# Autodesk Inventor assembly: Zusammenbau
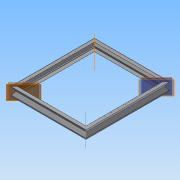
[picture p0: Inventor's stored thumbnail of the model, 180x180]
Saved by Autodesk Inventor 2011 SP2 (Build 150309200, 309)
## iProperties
Created: 2009-11
Part Number: Zusammenbau
Document SubType Name: Assembly
Designer: gkramp
Author: gkramp
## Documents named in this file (4)
- D:\InventorSchulung\Zusammenbau_Beispiel_Master\Zusammenbau.iam
- D:\InventorSchulung\Zusammenbau_Beispiel_Master\Masterbaugruppe.iam
- D:\InventorSchulung\Zusammenbau_Beispiel_Master\Rahmen_mit_Löchern.ipt
- D:\InventorSchulung\Zusammenbau_Beispiel_Master\Rahmen_ohne_Löcher.ipt
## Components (5 placed, 3 different names)
1. Masterbaugruppe:1 [sub-assembly] — Fluchtend:3
2. Rahmen_mit_Löchern:1 — Passend:1, Passend:2, Fluchtend:4, Passend:3
3. Rahmen_mit_Löchern:2 — Fluchtend:3, Fluchtend:4
4. Rahmen_ohne_Löcher:1 — Passend:3, Fluchtend:5, Fluchtend:6
5. Rahmen_ohne_Löcher:2 — Passend:4, Fluchtend:7, Passend:5
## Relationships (10: Flush 5, Mate 5)
- Fluchtend:3 [Flush]: Masterbaugruppe:1 ↔ Rahmen_mit_Löchern:2
- Passend:1 [Mate]: Rahmen_mit_Löchern:1
- Passend:2 [Mate]: Rahmen_mit_Löchern:1
- Fluchtend:4 [Flush]: Rahmen_mit_Löchern:1 ↔ Rahmen_mit_Löchern:2
- Passend:3 [Mate]: Rahmen_mit_Löchern:1 ↔ Rahmen_ohne_Löcher:1
- Fluchtend:5 [Flush]: Rahmen_ohne_Löcher:1
- Fluchtend:6 [Flush]: Rahmen_ohne_Löcher:1
- Passend:4 [Mate]: Rahmen_ohne_Löcher:2
- Fluchtend:7 [Flush]: Rahmen_ohne_Löcher:2
- Passend:5 [Mate]: Rahmen_ohne_Löcher:2
